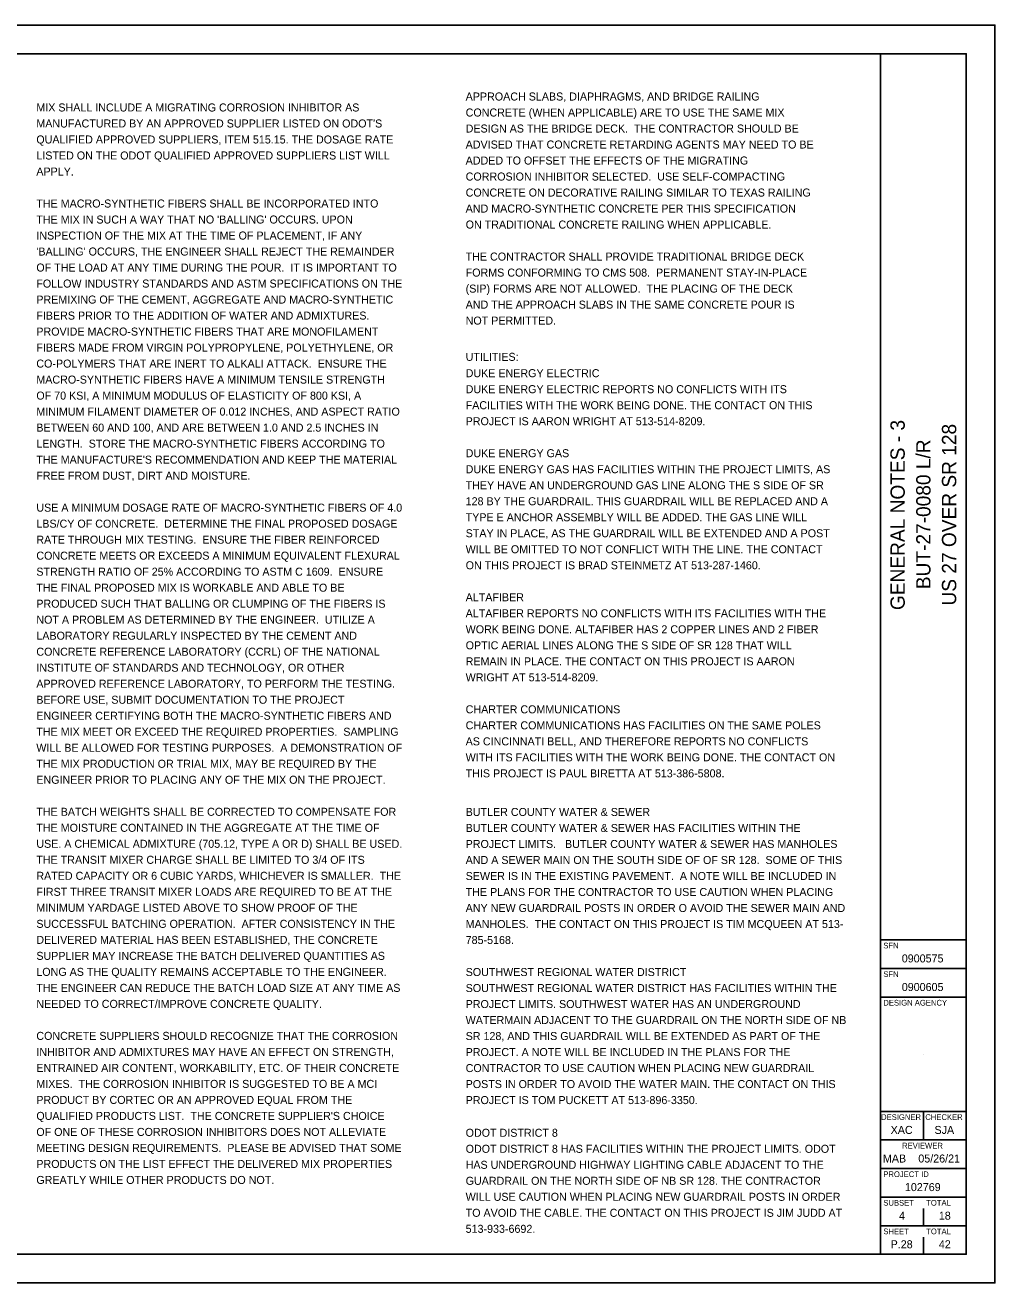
# Model space of a CAD drawing. Extents: x 0 to 442, y -35 to 22.
# Drawn here: x 17.04 to 34, y 0 to 22 of the extents above; entities that cross this region are included whole.
import ezdxf

# ---------------------------------------------------------------- set-up
doc = ezdxf.new("R2010")
doc.units = 0
for name, color, linetype in [('BR_P_Gen_Text', 7, 'Continuous'), ('SH_Border', 7, 'Continuous'), ('SH_Cut_Line', 7, 'Continuous'), ('SH_Data', 7, 'Continuous'), ('SH_Text', 7, 'Continuous')]:
    doc.layers.add(name, color=color, linetype=linetype)

msp = doc.modelspace()

# ---------------------------------------------------------------- linework, layer by layer
at = {"layer": 'SH_Border'}
for p, q in [((32.75, 5.675), (32.75, 5.675)), ((32.75, 5.175), (32.75, 5.175)), ((32.75, 4), (32.75, 4)), ((32.75, 1), (32.75, 1.3)), ((32.375, 0.675), (32.375, 0.675)), ((32.75, 0.5), (32.75, 0.8))]:
    msp.add_line(p, q, dxfattribs=at)
at = {"layer": 'SH_Cut_Line'}
msp.add_lwpolyline([(0, 0), (34, 0), (34, 22), (0, 22)], close=True, dxfattribs=at)
at = {"layer": 'SH_Data'}
for p, q in [((32, 0.5), (32, 21.5)), ((32, 6), (33.5, 6)), ((32, 5.5), (33.5, 5.5)), ((32, 5), (33.5, 5)), ((32, 3), (33.5, 3)), ((32.75, 3), (32.75, 2.5)), ((32, 2.5), (33.5, 2.5)), ((32, 2), (33.5, 2)), ((32, 1.5), (33.5, 1.5)), ((32, 1), (33.5, 1))]:
    msp.add_line(p, q, dxfattribs=at)
msp.add_lwpolyline([(1.5, 21.5), (33.5, 21.5), (33.5, 0.5), (1.5, 0.5)], close=True, dxfattribs=at)

# ---------------------------------------------------------------- texts
at = {"layer": 'BR_P_Gen_Text'}
for s, p in [('UTILITIES:', (24.747, 16.128)), ('DUKE ENERGY ELECTRIC', (24.747, 15.842)), ('DUKE ENERGY ELECTRIC REPORTS NO CONFLICTS WITH ITS ', (24.747, 15.562)), ('FACILITIES WITH THE WORK BEING DONE. THE CONTACT ON THIS ', (24.747, 15.282)), ('PROJECT IS AARON WRIGHT AT 513-514-8209.', (24.747, 15.002)), ('DUKE ENERGY GAS', (24.747, 14.442)), ('DUKE ENERGY GAS HAS FACILITIES WITHIN THE PROJECT LIMITS, AS ', (24.747, 14.162)), ('THEY HAVE AN UNDERGROUND GAS LINE ALONG THE S SIDE OF SR ', (24.747, 13.882)), ('128 BY THE GUARDRAIL. THIS GUARDRAIL WILL BE REPLACED AND A ', (24.747, 13.602)), ('TYPE E ANCHOR ASSEMBLY WILL BE ADDED. THE GAS LINE WILL ', (24.747, 13.322)), ('STAY IN PLACE, AS THE GUARDRAIL WILL BE EXTENDED AND A POST ', (24.747, 13.042)), ('WILL BE OMITTED TO NOT CONFLICT WITH THE LINE. THE CONTACT ', (24.747, 12.762)), ('ON THIS PROJECT IS BRAD STEINMETZ AT 513-287-1460.', (24.747, 12.482)), ('ALTAFIBER', (24.747, 11.922)), ('ALTAFIBER REPORTS NO CONFLICTS WITH ITS FACILITIES WITH THE ', (24.747, 11.642)), ('WORK BEING DONE. ALTAFIBER HAS 2 COPPER LINES AND 2 FIBER ', (24.747, 11.362)), ('OPTIC AERIAL LINES ALONG THE S SIDE OF SR 128 THAT WILL ', (24.747, 11.082)), ('REMAIN IN PLACE. THE CONTACT ON THIS PROJECT IS AARON ', (24.747, 10.802)), ('WRIGHT AT 513-514-8209.', (24.747, 10.522)), ('CHARTER COMMUNICATIONS', (24.747, 9.962)), ('CHARTER COMMUNICATIONS HAS FACILITIES ON THE SAME POLES ', (24.747, 9.682)), ('AS CINCINNATI BELL, AND THEREFORE REPORTS NO CONFLICTS ', (24.747, 9.402)), ('WITH ITS FACILITIES WITH THE WORK BEING DONE. THE CONTACT ON ', (24.747, 9.122)), ('THIS PROJECT IS PAUL BIRETTA AT 513-386-5808.', (24.747, 8.842)), ('BUTLER COUNTY WATER & SEWER', (24.747, 8.167)), ('BUTLER COUNTY WATER & SEWER HAS FACILITIES WITHIN THE ', (24.747, 7.887)), ('PROJECT LIMITS.   BUTLER COUNTY WATER & SEWER HAS MANHOLES ', (24.747, 7.607)), ('AND A SEWER MAIN ON THE SOUTH SIDE OF OF SR 128.  SOME OF THIS ', (24.747, 7.327)), ('SEWER IS IN THE EXISTING PAVEMENT.  A NOTE WILL BE INCLUDED IN ', (24.747, 7.047)), ('THE PLANS FOR THE CONTRACTOR TO USE CAUTION WHEN PLACING ', (24.747, 6.767)), ('ANY NEW GUARDRAIL POSTS IN ORDER O AVOID THE SEWER MAIN AND ', (24.747, 6.487)), ('MANHOLES.  THE CONTACT ON THIS PROJECT IS TIM MCQUEEN AT 513-', (24.747, 6.207)), ('785-5168.', (24.747, 5.927)), ('SOUTHWEST REGIONAL WATER DISTRICT', (24.747, 5.367)), ('SOUTHWEST REGIONAL WATER DISTRICT HAS FACILITIES WITHIN THE ', (24.747, 5.087)), ('PROJECT LIMITS. SOUTHWEST WATER HAS AN UNDERGROUND ', (24.747, 4.807)), ('WATERMAIN ADJACENT TO THE GUARDRAIL ON THE NORTH SIDE OF NB ', (24.747, 4.527)), ('SR 128, AND THIS GUARDRAIL WILL BE EXTENDED AS PART OF THE ', (24.747, 4.247)), ('PROJECT. A NOTE WILL BE INCLUDED IN THE PLANS FOR THE ', (24.747, 3.967)), ('CONTRACTOR TO USE CAUTION WHEN PLACING NEW GUARDRAIL ', (24.747, 3.687)), ('POSTS IN ORDER TO AVOID THE WATER MAIN. THE CONTACT ON THIS ', (24.747, 3.407)), ('PROJECT IS TOM PUCKETT AT 513-896-3350.', (24.747, 3.127)), ('ODOT DISTRICT 8', (24.747, 2.555)), ('ODOT DISTRICT 8 HAS FACILITIES WITHIN THE PROJECT LIMITS. ODOT ', (24.747, 2.275)), ('HAS UNDERGROUND HIGHWAY LIGHTING CABLE ADJACENT TO THE ', (24.747, 1.995)), ('GUARDRAIL ON THE NORTH SIDE OF NB SR 128. THE CONTRACTOR ', (24.747, 1.715)), ('WILL USE CAUTION WHEN PLACING NEW GUARDRAIL POSTS IN ORDER ', (24.747, 1.435)), ('TO AVOID THE CABLE. THE CONTACT ON THIS PROJECT IS JIM JUDD AT ', (24.747, 1.155)), ('513-933-6692.', (24.747, 0.875))]:
    msp.add_text(s, height=0.14, dxfattribs=at).set_placement(p)
at = {"layer": 'SH_Border'}
for s, p in [('GENERAL NOTES - 3', (32.425, 11.769)), ('US 27 OVER SR 128', (33.325, 11.848)), ('BUT-27-0080 L/R', (32.875, 12.134))]:
    msp.add_text(s, height=0.25, rotation=90, dxfattribs=at).set_placement(p)
for s, height, p in [('SFN', 0.1, (32.05, 5.85)), ('0900575', 0.14, (32.373, 5.605)), ('SFN', 0.1, (32.05, 5.35)), ('0900605', 0.14, (32.373, 5.105)), ('DESIGN AGENCY', 0.1, (32.05, 4.85)), ('DESIGNER', 0.1, (32.011, 2.85)), ('CHECKER', 0.1, (32.784, 2.85)), ('XAC', 0.14, (32.178, 2.605)), ('SJA', 0.14, (32.945, 2.605)), ('REVIEWER', 0.1, (32.378, 2.35)), ('MAB', 0.14, (32.043, 2.105)), ('05/26/21', 0.14, (32.662, 2.105)), ('PROJECT ID', 0.1, (32.05, 1.85)), ('102769', 0.14, (32.428, 1.605)), ('SUBSET', 0.1, (32.05, 1.35)), ('TOTAL', 0.1, (32.8, 1.35)), ('4', 0.14, (32.325, 1.105)), ('18', 0.14, (33.021, 1.105)), ('SHEET', 0.1, (32.05, 0.85)), ('TOTAL', 0.1, (32.8, 0.85)), ('P.28', 0.14, (32.178, 0.605)), ('42', 0.14, (33.021, 0.605))]:
    msp.add_text(s, height=height, dxfattribs=at).set_placement(p)
at = {"layer": 'SH_Text'}
for s, p in [('APPROACH SLABS, DIAPHRAGMS, AND BRIDGE RAILING ', (24.747, 20.682)), ('MIX SHALL INCLUDE A MIGRATING CORROSION INHIBITOR AS ', (17.24, 20.49)), ('CONCRETE (WHEN APPLICABLE) ARE TO USE THE SAME MIX ', (24.747, 20.402)), ("MANUFACTURED BY AN APPROVED SUPPLIER LISTED ON ODOT'S ", (17.24, 20.21)), ('DESIGN AS THE BRIDGE DECK.  THE CONTRACTOR SHOULD BE ', (24.747, 20.122)), ('QUALIFIED APPROVED SUPPLIERS, ITEM 515.15. THE DOSAGE RATE ', (17.24, 19.93)), ('ADVISED THAT CONCRETE RETARDING AGENTS MAY NEED TO BE ', (24.747, 19.842)), ('LISTED ON THE ODOT QUALIFIED APPROVED SUPPLIERS LIST WILL ', (17.24, 19.65)), ('ADDED TO OFFSET THE EFFECTS OF THE MIGRATING ', (24.747, 19.562)), ('APPLY.  ', (17.24, 19.37)), ('CORROSION INHIBITOR SELECTED.  USE SELF-COMPACTING ', (24.747, 19.282)), ('CONCRETE ON DECORATIVE RAILING SIMILAR TO TEXAS RAILING ', (24.747, 19.002)), ('THE MACRO-SYNTHETIC FIBERS SHALL BE INCORPORATED INTO ', (17.24, 18.81)), ('AND MACRO-SYNTHETIC CONCRETE PER THIS SPECIFICATION ', (24.747, 18.722)), ("THE MIX IN SUCH A WAY THAT NO 'BALLING' OCCURS. UPON ", (17.24, 18.53)), ('ON TRADITIONAL CONCRETE RAILING WHEN APPLICABLE.', (24.747, 18.442)), ('INSPECTION OF THE MIX AT THE TIME OF PLACEMENT, IF ANY ', (17.24, 18.25)), ("'BALLING' OCCURS, THE ENGINEER SHALL REJECT THE REMAINDER ", (17.24, 17.97)), ('OF THE LOAD AT ANY TIME DURING THE POUR.  IT IS IMPORTANT TO ', (17.24, 17.69)), ('THE CONTRACTOR SHALL PROVIDE TRADITIONAL BRIDGE DECK ', (24.747, 17.882)), ('FORMS CONFORMING TO CMS 508.  PERMANENT STAY-IN-PLACE ', (24.747, 17.602)), ('FOLLOW INDUSTRY STANDARDS AND ASTM SPECIFICATIONS ON THE ', (17.24, 17.41)), ('(SIP) FORMS ARE NOT ALLOWED.  THE PLACING OF THE DECK ', (24.747, 17.322)), ('PREMIXING OF THE CEMENT, AGGREGATE AND MACRO-SYNTHETIC ', (17.24, 17.13)), ('AND THE APPROACH SLABS IN THE SAME CONCRETE POUR IS ', (24.747, 17.042)), ('FIBERS PRIOR TO THE ADDITION OF WATER AND ADMIXTURES. ', (17.24, 16.85)), ('NOT PERMITTED.', (24.747, 16.762)), ('PROVIDE MACRO-SYNTHETIC FIBERS THAT ARE MONOFILAMENT ', (17.24, 16.57)), ('FIBERS MADE FROM VIRGIN POLYPROPYLENE, POLYETHYLENE, OR ', (17.24, 16.29)), ('CO-POLYMERS THAT ARE INERT TO ALKALI ATTACK.  ENSURE THE ', (17.24, 16.01)), ('MACRO-SYNTHETIC FIBERS HAVE A MINIMUM TENSILE STRENGTH ', (17.24, 15.73)), ('OF 70 KSI, A MINIMUM MODULUS OF ELASTICITY OF 800 KSI, A ', (17.24, 15.45)), ('MINIMUM FILAMENT DIAMETER OF 0.012 INCHES, AND ASPECT RATIO ', (17.24, 15.17)), ('BETWEEN 60 AND 100, AND ARE BETWEEN 1.0 AND 2.5 INCHES IN ', (17.24, 14.89)), ('LENGTH.  STORE THE MACRO-SYNTHETIC FIBERS ACCORDING TO ', (17.24, 14.61)), ("THE MANUFACTURE'S RECOMMENDATION AND KEEP THE MATERIAL ", (17.24, 14.33)), ('FREE FROM DUST, DIRT AND MOISTURE.', (17.24, 14.05)), ('USE A MINIMUM DOSAGE RATE OF MACRO-SYNTHETIC FIBERS OF 4.0 ', (17.24, 13.49)), ('LBS/CY OF CONCRETE.  DETERMINE THE FINAL PROPOSED DOSAGE ', (17.24, 13.21)), ('RATE THROUGH MIX TESTING.  ENSURE THE FIBER REINFORCED ', (17.24, 12.93)), ('CONCRETE MEETS OR EXCEEDS A MINIMUM EQUIVALENT FLEXURAL ', (17.24, 12.65)), ('STRENGTH RATIO OF 25% ACCORDING TO ASTM C 1609.  ENSURE ', (17.24, 12.37)), ('THE FINAL PROPOSED MIX IS WORKABLE AND ABLE TO BE ', (17.24, 12.09)), ('PRODUCED SUCH THAT BALLING OR CLUMPING OF THE FIBERS IS ', (17.24, 11.81)), ('NOT A PROBLEM AS DETERMINED BY THE ENGINEER.  UTILIZE A ', (17.24, 11.53)), ('LABORATORY REGULARLY INSPECTED BY THE CEMENT AND ', (17.24, 11.25)), ('CONCRETE REFERENCE LABORATORY (CCRL) OF THE NATIONAL ', (17.24, 10.97)), ('INSTITUTE OF STANDARDS AND TECHNOLOGY, OR OTHER ', (17.24, 10.69)), ('APPROVED REFERENCE LABORATORY, TO PERFORM THE TESTING.  ', (17.24, 10.41)), ('BEFORE USE, SUBMIT DOCUMENTATION TO THE PROJECT ', (17.24, 10.13)), ('ENGINEER CERTIFYING BOTH THE MACRO-SYNTHETIC FIBERS AND ', (17.24, 9.85)), ('THE MIX MEET OR EXCEED THE REQUIRED PROPERTIES.  SAMPLING ', (17.24, 9.57)), ('WILL BE ALLOWED FOR TESTING PURPOSES.  A DEMONSTRATION OF ', (17.24, 9.29)), ('THE MIX PRODUCTION OR TRIAL MIX, MAY BE REQUIRED BY THE ', (17.24, 9.01)), ('ENGINEER PRIOR TO PLACING ANY OF THE MIX ON THE PROJECT.', (17.24, 8.73)), ('THE BATCH WEIGHTS SHALL BE CORRECTED TO COMPENSATE FOR ', (17.24, 8.17)), ('THE MOISTURE CONTAINED IN THE AGGREGATE AT THE TIME OF ', (17.24, 7.89)), ('USE. A CHEMICAL ADMIXTURE (705.12, TYPE A OR D) SHALL BE USED. ', (17.24, 7.61)), ('THE TRANSIT MIXER CHARGE SHALL BE LIMITED TO 3/4 OF ITS ', (17.24, 7.33)), ('RATED CAPACITY OR 6 CUBIC YARDS, WHICHEVER IS SMALLER.  THE ', (17.24, 7.05)), ('FIRST THREE TRANSIT MIXER LOADS ARE REQUIRED TO BE AT THE ', (17.24, 6.77)), ('MINIMUM YARDAGE LISTED ABOVE TO SHOW PROOF OF THE ', (17.24, 6.49)), ('SUCCESSFUL BATCHING OPERATION.  AFTER CONSISTENCY IN THE ', (17.24, 6.21)), ('DELIVERED MATERIAL HAS BEEN ESTABLISHED, THE CONCRETE ', (17.24, 5.93)), ('SUPPLIER MAY INCREASE THE BATCH DELIVERED QUANTITIES AS ', (17.24, 5.65)), ('LONG AS THE QUALITY REMAINS ACCEPTABLE TO THE ENGINEER.  ', (17.24, 5.37)), ('THE ENGINEER CAN REDUCE THE BATCH LOAD SIZE AT ANY TIME AS ', (17.24, 5.09)), ('NEEDED TO CORRECT/IMPROVE CONCRETE QUALITY.', (17.24, 4.81)), ('CONCRETE SUPPLIERS SHOULD RECOGNIZE THAT THE CORROSION ', (17.24, 4.25)), ('INHIBITOR AND ADMIXTURES MAY HAVE AN EFFECT ON STRENGTH, ', (17.24, 3.97)), ('ENTRAINED AIR CONTENT, WORKABILITY, ETC. OF THEIR CONCRETE ', (17.24, 3.69)), ('MIXES.  THE CORROSION INHIBITOR IS SUGGESTED TO BE A MCI ', (17.24, 3.41)), ('PRODUCT BY CORTEC OR AN APPROVED EQUAL FROM THE ', (17.24, 3.13)), ("QUALIFIED PRODUCTS LIST.  THE CONCRETE SUPPLIER'S CHOICE ", (17.24, 2.85)), ('OF ONE OF THESE CORROSION INHIBITORS DOES NOT ALLEVIATE ', (17.24, 2.57)), ('MEETING DESIGN REQUIREMENTS.  PLEASE BE ADVISED THAT SOME ', (17.24, 2.29)), ('PRODUCTS ON THE LIST EFFECT THE DELIVERED MIX PROPERTIES ', (17.24, 2.01)), ('GREATLY WHILE OTHER PRODUCTS DO NOT.', (17.24, 1.73))]:
    msp.add_text(s, height=0.14, dxfattribs=at).set_placement(p)

doc.saveas('drawing.dxf')
